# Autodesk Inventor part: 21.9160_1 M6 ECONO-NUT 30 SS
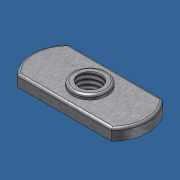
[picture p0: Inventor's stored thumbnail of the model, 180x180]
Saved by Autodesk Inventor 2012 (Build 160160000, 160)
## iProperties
Created: 2013-11
Part Number: 21.9160_1 M6 ECONO-NUT 30 SS
Material: Stainless Steel
Document SubType Name: Modeling
Designer: Admin
Density: 7.75 g/cm^3
Mass: 4.94253 g
Surface Area: 7.16871 cm^2
Volume: 0.637746 cm^3
Author: Admin
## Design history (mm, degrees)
sketch "Sketch1"
  geometry: L1 (-10.25, 5.6)-(10.25, 5.6); L2 (-10.25, -5.6)-(10.25, -5.6); L3 (-4.753, 0)-(4.753, 0); A1 r 7.847 centre (-4.753, 0) between (-10.25, 5.6) and (-10.25, -5.6); A2 r 7.847 centre (4.753, 0) between (10.25, -5.6) and (10.25, 5.6); 2 further points
  constraints: 6 end point, 4 point on circle, 2 centre point, 2 horizontal, 1 coincident, 1 equal radius, 1 horizontal alignment, 1 midpoint, 1 parallel
  dimensions: "d0" = 11.2 distance between parallel lines of L2 L1; "d1" = 25.2 dimension on A2 A1; "d2" = 5.6 distance from line of point (0, 0) L1 (= 0.5 x d0); "d3" = 20.5 distance of L1.start L1.end
extrude "Extrusion1" new body sketch "Sketch1" distance "d4" = 2.5; taper "d5" = 0 deg
sketch "Sketch2"
  geometry: C1 r 3.75 at (0, 0); 1 further point
  constraints: 1 centre point, 1 coincident
  dimensions: "d6" = 7.5 diameter of C1
extrude "Extrusion2" join sketch "Sketch2" distance "d7" = 1; taper "d8" = 0 deg
sketch "Sketch3"
  geometry: C1 r 3.75 at (0, 0) reference; 1 further point
  constraints: 1 coincident
hole "Hole1" sketch "Sketch3" at (0, 0) diameter "d9" = 4.917; stored, may be unused: countersink angle "d13" = 90 deg, drill point angle "d15" = 118 deg; dims "d10" = 6, "d11" = 4, "d12" = 2, "d14" = 8
fillet "Fillet1" dims "d16" = 0.5
body "Solid1"
